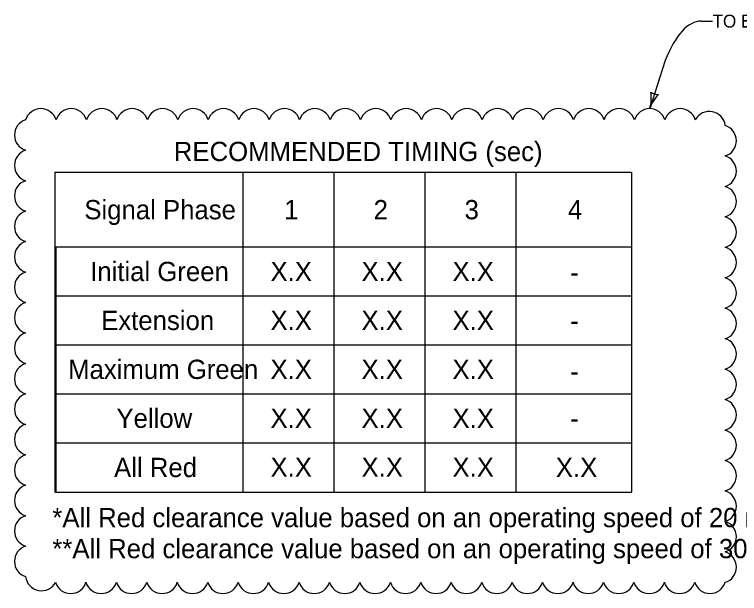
# Model space of a CAD drawing. Extents: x -2134934 to -2122394, y -2140205 to -2137036.
# Drawn here: x -2134270 to -2133366, y -2140170 to -2139448 of the extents above; entities that cross this region are included whole.
import ezdxf

# ---------------------------------------------------------------- set-up
doc = ezdxf.new("R2010")
doc.units = 0
doc.layers.add('BridgeSuperStructureExisting', color=7, linetype='Continuous')
doc.layers.add('dsnStdLabel', color=7, linetype='Continuous')

msp = doc.modelspace()

# ---------------------------------------------------------------- linework, layer by layer
at = {"layer": 'BridgeSuperStructureExisting'}
for p, q in [((-2133413.58, -2139456.16), (-2133399.36, -2139456.16)), ((-2133458.31, -2139505.29), (-2133477.71, -2139565.29)), ((-2134219.67, -2139644.69), (-2134219.67, -2140043.51)), ((-2134219.67, -2139644.69), (-2133500.54, -2139644.69)), ((-2133985.35, -2139644.69), (-2133985.35, -2140043.51)), ((-2133871.85, -2139644.69), (-2133871.85, -2140043.51)), ((-2133758.35, -2139644.69), (-2133758.35, -2140043.51)), ((-2133644.85, -2139644.69), (-2133644.85, -2140043.51)), ((-2133500.54, -2139644.69), (-2133500.54, -2140043.51)), ((-2134218.43, -2139737.78), (-2133500.54, -2139737.78)), ((-2134218.43, -2139737.78), (-2134218.43, -2139798.78)), ((-2134218.43, -2139798.78), (-2134218.43, -2139859.78)), ((-2134218.43, -2139798.78), (-2133500.54, -2139798.78)), ((-2134218.43, -2139859.78), (-2134218.43, -2139920.78)), ((-2134218.43, -2139859.78), (-2133500.54, -2139859.78)), ((-2134218.43, -2139920.78), (-2134218.43, -2139981.78)), ((-2134218.43, -2139920.78), (-2133500.54, -2139920.78)), ((-2134218.43, -2139981.78), (-2134218.43, -2140042.78)), ((-2134218.43, -2139981.78), (-2133500.54, -2139981.78)), ((-2134219.67, -2140043.51), (-2133500.54, -2140043.51))]:
    msp.add_line(p, q, dxfattribs=at)
for centre, radius, start, end in [((-2133518.15, -2139552.21), 42.5, 342.08492, 10.15741), ((-2133437.27, -2139578.36), 42.5, 134.01243, 162.08492), ((-2133466.75, -2139531.38), 16.42, 234.35157, 269.81827), ((-2134237.11, -2139585.19), 19.91, 17.5, 162.5), ((-2134199.14, -2139585.19), 19.91, 17.5, 162.5), ((-2134161.17, -2139585.19), 19.91, 17.5, 162.5), ((-2134123.2, -2139585.19), 19.91, 17.5, 162.5), ((-2134085.23, -2139585.19), 19.91, 17.5, 162.5), ((-2134047.26, -2139585.19), 19.91, 17.5, 162.5), ((-2134009.29, -2139585.19), 19.91, 17.5, 162.5), ((-2133971.32, -2139585.19), 19.91, 17.5, 162.5), ((-2133933.35, -2139585.19), 19.91, 17.5, 162.5), ((-2133895.38, -2139585.19), 19.91, 17.5, 162.5), ((-2133857.41, -2139585.19), 19.91, 17.5, 162.5), ((-2133819.44, -2139585.19), 19.91, 17.5, 162.5), ((-2133781.47, -2139585.19), 19.91, 17.5, 162.5), ((-2133743.5, -2139585.19), 19.91, 17.5, 162.5), ((-2133705.53, -2139585.19), 19.91, 17.5, 162.5), ((-2133667.56, -2139585.19), 19.91, 17.5, 162.5), ((-2133629.59, -2139585.19), 19.91, 17.5, 162.5), ((-2133591.62, -2139585.19), 19.91, 17.5, 162.5), ((-2133553.65, -2139585.19), 19.91, 17.5, 162.5), ((-2133515.68, -2139585.19), 19.91, 17.5, 162.5), ((-2133477.71, -2139585.19), 19.91, 17.5, 162.5), ((-2133439.74, -2139585.19), 19.91, 17.5, 162.5), ((-2133403.23, -2139588.64), 19.9, 6.71063, 151.71063), ((-2134250.11, -2139598.19), 19.91, 107.5, 252.5), ((-2133389.46, -2139605.3), 19.91, 287.5, 72.5), ((-2134250.11, -2139636.16), 19.91, 107.5, 252.5), ((-2133389.46, -2139643.27), 19.91, 287.5, 72.5), ((-2134250.11, -2139674.13), 19.91, 107.5, 252.5), ((-2133389.46, -2139681.24), 19.91, 287.5, 72.5), ((-2134250.11, -2139712.1), 19.91, 107.5, 252.5), ((-2133389.46, -2139719.21), 19.91, 287.5, 72.5), ((-2134250.11, -2139750.07), 19.91, 107.5, 252.5), ((-2133389.46, -2139757.18), 19.91, 287.5, 72.5), ((-2134250.11, -2139788.04), 19.91, 107.5, 252.5), ((-2133389.46, -2139795.15), 19.91, 287.5, 72.5), ((-2134250.11, -2139826.01), 19.91, 107.5, 252.5), ((-2133389.46, -2139833.12), 19.91, 287.5, 72.5), ((-2134250.11, -2139863.98), 19.91, 107.5, 252.5), ((-2133389.46, -2139871.09), 19.91, 287.5, 72.5), ((-2134250.11, -2139901.95), 19.91, 107.5, 252.5), ((-2133389.46, -2139909.06), 19.91, 287.5, 72.5), ((-2134250.11, -2139939.92), 19.91, 107.5, 252.5), ((-2133389.46, -2139947.03), 19.91, 287.5, 72.5), ((-2134250.11, -2139977.89), 19.91, 107.5, 252.5), ((-2133389.46, -2139985), 19.91, 287.5, 72.5), ((-2134250.11, -2140015.86), 19.91, 107.5, 252.5), ((-2133389.46, -2140022.97), 19.91, 287.5, 72.5), ((-2134250.11, -2140053.83), 19.91, 107.5, 252.5), ((-2133389.46, -2140060.94), 19.91, 287.5, 72.5), ((-2134250.11, -2140091.8), 19.91, 107.5, 252.5), ((-2133389.46, -2140098.91), 19.91, 287.5, 72.5), ((-2134250.11, -2140129.77), 19.91, 107.5, 252.5), ((-2133389.46, -2140136.88), 19.91, 287.5, 72.5), ((-2134236.33, -2140146.43), 19.9, 186.71063, 331.71063), ((-2134199.83, -2140149.88), 19.91, 197.5, 342.5), ((-2134161.86, -2140149.88), 19.91, 197.5, 342.5), ((-2134123.89, -2140149.88), 19.91, 197.5, 342.5), ((-2134085.92, -2140149.88), 19.91, 197.5, 342.5), ((-2134047.95, -2140149.88), 19.91, 197.5, 342.5), ((-2134009.98, -2140149.88), 19.91, 197.5, 342.5), ((-2133972.01, -2140149.88), 19.91, 197.5, 342.5), ((-2133934.04, -2140149.88), 19.91, 197.5, 342.5), ((-2133896.07, -2140149.88), 19.91, 197.5, 342.5), ((-2133858.1, -2140149.88), 19.91, 197.5, 342.5), ((-2133820.13, -2140149.88), 19.91, 197.5, 342.5), ((-2133782.16, -2140149.88), 19.91, 197.5, 342.5), ((-2133744.19, -2140149.88), 19.91, 197.5, 342.5), ((-2133706.22, -2140149.88), 19.91, 197.5, 342.5), ((-2133668.25, -2140149.88), 19.91, 197.5, 342.5), ((-2133630.28, -2140149.88), 19.91, 197.5, 342.5), ((-2133592.31, -2140149.88), 19.91, 197.5, 342.5), ((-2133554.34, -2140149.88), 19.91, 197.5, 342.5), ((-2133516.37, -2140149.88), 19.91, 197.5, 342.5), ((-2133478.4, -2140149.88), 19.91, 197.5, 342.5), ((-2133440.43, -2140149.88), 19.91, 197.5, 342.5), ((-2133402.46, -2140149.88), 19.91, 197.5, 342.5)]:
    msp.add_arc(centre, radius, start, end, dxfattribs=at)
msp.add_ellipse((-2133413.58, -2139669.09), major_axis=(0, 212.93), ratio=0.328743, start_param=0, end_param=0.693162, dxfattribs=at)

# ---------------------------------------------------------------- texts
msp.add_text('TO BE UPDATED ONCE TIMING PROVIDED BY IOWA DOT', height=16, dxfattribs=at).set_placement((-2133399.36, -2139464.16))
at = {"layer": 'dsnStdLabel'}
for s, p in [('RECOMMENDED TIMING (sec)', (-2134071.3, -2139630.67)), ('Signal Phase', (-2134182.91, -2139703.23)), ('1', (-2133933.7, -2139703.23)), ('2', (-2133822.02, -2139703.23)), ('3', (-2133708.59, -2139703.23)), ('4', (-2133579.66, -2139703.23)), ('Initial Green', (-2134175.67, -2139780.28)), ('X.X', (-2133950.68, -2139780.28)), ('X.X', (-2133837.18, -2139780.28)), ('X.X', (-2133723.68, -2139780.28)), ('-', (-2133576.84, -2139781.31)), ('Extension', (-2134161.92, -2139841.28)), ('X.X', (-2133950.68, -2139841.28)), ('X.X', (-2133837.18, -2139841.28)), ('X.X', (-2133723.68, -2139841.28)), ('-', (-2133576.84, -2139841.66)), ('Maximum Green', (-2134203.15, -2139902.28)), ('X.X', (-2133950.68, -2139902.28)), ('X.X', (-2133837.18, -2139902.28)), ('X.X', (-2133723.68, -2139902.28)), ('-', (-2133576.84, -2139904.72)), ('Yellow', (-2134142.86, -2139963.28)), ('X.X', (-2133950.68, -2139963.28)), ('X.X', (-2133837.18, -2139963.28)), ('X.X', (-2133723.68, -2139963.28)), ('-', (-2133576.84, -2139963.28)), ('All Red', (-2134145.81, -2140024.64)), ('X.X', (-2133950.68, -2140024.28)), ('X.X', (-2133837.18, -2140024.28)), ('X.X', (-2133723.68, -2140024.28)), ('X.X', (-2133594.77, -2140024.64)), ('*All Red clearance value based on an operating speed of 20 mph.', (-2134222.8, -2140087.12)), ('**All Red clearance value based on an operating speed of 30 mph.', (-2134222.8, -2140125.8))]:
    msp.add_text(s, height=24, dxfattribs=at).set_placement(p)

doc.saveas('drawing.dxf')
